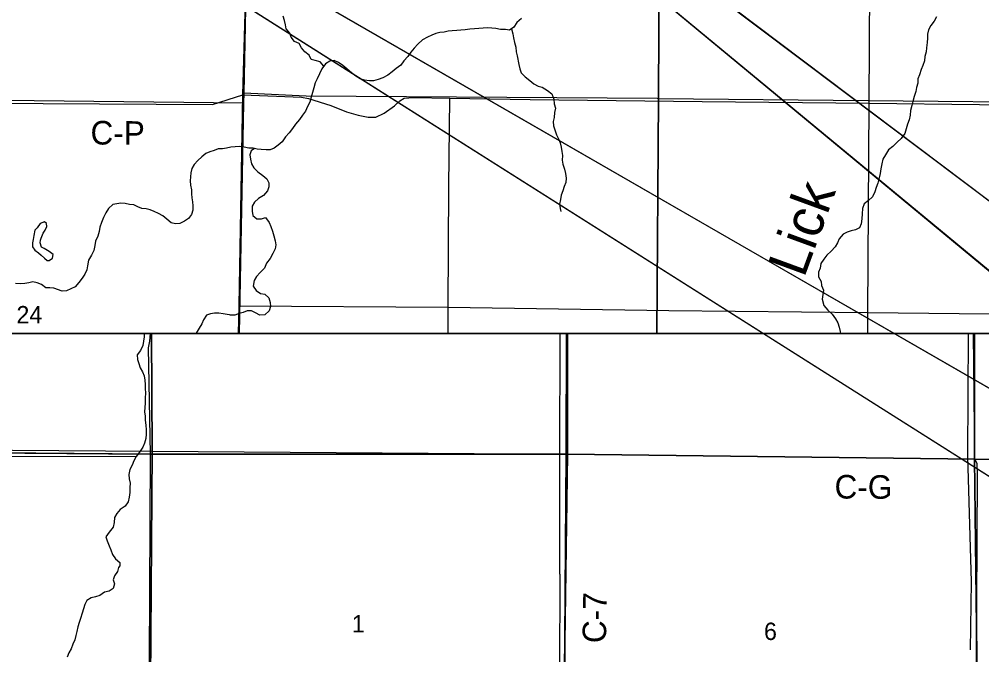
# Model space of a CAD drawing. Extents: x -6.2 to 37.4, y 0.2 to 22.2.
# Drawn here: x 6.554 to 7.714, y 17.321 to 18.086 of the extents above; entities that cross this region are included whole.
import ezdxf

# ---------------------------------------------------------------- set-up
doc = ezdxf.new("R2010")
doc.units = 0
for name, color, linetype in [('GM_X_County_Road', 7, 'Continuous'), ('GM_X_County_Road_Text', 7, 'Continuous'), ('GM_X_Minor_Lake', 7, 'Continuous'), ('GM_X_Minor_River', 7, 'Continuous'), ('GM_X_Minor_River_Text', 7, 'Continuous'), ('GM_X_Rail_Line', 7, 'Continuous'), ('GM_X_Section', 7, 'Continuous'), ('GM_X_Section_Text', 7, 'Continuous'), ('GM_X_Township_Road', 7, 'Continuous'), ('GM_X_US_Shield', 7, 'Continuous'), ('SH_Border', 7, 'Continuous'), ('SH_Cut_Line', 7, 'Continuous'), ('SH_Data', 7, 'Continuous')]:
    doc.layers.add(name, color=color, linetype=linetype)

msp = doc.modelspace()

# ---------------------------------------------------------------- linework, layer by layer
at = {"layer": 'GM_X_County_Road'}
for p, q in [((7.215, 17.5619), (7.2148, 17.7074)), ((7.7056, 17.556), (7.704, 17.7074)), ((7.2115, 17.3074), (7.215, 17.5619))]:
    msp.add_line(p, q, dxfattribs=at)
for points in [[(6.8186, 17.7074), (6.8192, 17.7406), (6.8236, 17.9946), (6.8304, 18.2331)], [(5.443, 17.9975), (5.458, 17.9973), (5.8185, 17.9939), (6.0806, 17.9898), (6.319, 17.9868), (6.5828, 17.9842), (6.7869, 17.983), (6.8236, 17.9946)], [(6.8236, 17.9946), (6.8942, 17.9919), (6.9025, 17.9903), (6.9295, 17.982), (6.9486, 17.9742), (6.9624, 17.9704), (6.9745, 17.9678), (6.9839, 17.9677), (6.994, 17.9727), (7.0064, 17.9815), (7.0126, 17.9877), (7.0179, 17.9909), (7.0293, 17.9915), (7.0729, 17.9907), (7.1697, 17.989), (7.3771, 17.9867), (7.5783, 17.9846)], [(7.5783, 17.9846), (7.8443, 17.9813), (8.1256, 17.9795), (8.3325, 17.9775)], [(6.7121, 17.5619), (6.7098, 17.69), (6.7113, 17.6982), (6.7121, 17.7074)], [(6.2071, 17.5661), (6.7121, 17.5619), (7.215, 17.5619)], [(6.7103, 17.0648), (6.7112, 17.3138), (6.7121, 17.5619)], [(7.215, 17.5619), (7.7056, 17.556), (7.9868, 17.5522), (8.2114, 17.551)], [(7.7089, 17.0636), (7.7076, 17.3026), (7.7087, 17.5373), (7.7083, 17.5507), (7.7056, 17.556)]]:
    msp.add_lwpolyline(points, dxfattribs=at)
at = {"layer": 'GM_X_Minor_Lake'}
msp.add_line((6.581, 17.8112), (6.5792, 17.8166), dxfattribs=at)
msp.add_lwpolyline([(6.5792, 17.8166), (6.5797, 17.8196), (6.5805, 17.8222), (6.5829, 17.8281), (6.5852, 17.8316), (6.5874, 17.8361), (6.5871, 17.8397), (6.5845, 17.8417), (6.5795, 17.8397), (6.5755, 17.8345), (6.5729, 17.8317), (6.5717, 17.8254), (6.5708, 17.8205), (6.5702, 17.8165), (6.5701, 17.8116), (6.573, 17.8078), (6.5775, 17.8043), (6.5804, 17.8015), (6.5847, 17.798), (6.5879, 17.7951), (6.5903, 17.7951), (6.5942, 17.7979), (6.595, 17.8024), (6.59, 17.8061), (6.584, 17.8096), (6.581, 17.8112)], dxfattribs=at)
at = {"layer": 'GM_X_Minor_River'}
for points in [[(7.1595, 18.0865), (7.1537, 18.0819), (7.1502, 18.0761), (7.1448, 18.0727), (7.1399, 18.0734), (7.134, 18.0735), (7.1286, 18.0747), (7.1236, 18.075), (7.1182, 18.0754), (7.1132, 18.0751), (7.1081, 18.0747), (7.1028, 18.0742), (7.0971, 18.0737), (7.0916, 18.073), (7.0864, 18.0724), (7.0815, 18.0722), (7.0758, 18.0718), (7.0709, 18.0713), (7.0661, 18.0702), (7.061, 18.0697), (7.056, 18.0687), (7.0513, 18.0667), (7.0459, 18.0641), (7.0402, 18.0611), (7.0346, 18.0559), (7.0301, 18.0509), (7.0261, 18.046), (7.0224, 18.0409), (7.0174, 18.0357), (7.0139, 18.0304), (7.0085, 18.0265), (7.0037, 18.0223), (6.9983, 18.0186), (6.9924, 18.0154), (6.9865, 18.0131), (6.9811, 18.0116), (6.976, 18.0115), (6.9703, 18.0124), (6.9649, 18.014), (6.9598, 18.0173), (6.9544, 18.0212), (6.949, 18.026), (6.9441, 18.0302), (6.9388, 18.0336), (6.9338, 18.0359), (6.9283, 18.0352), (6.9233, 18.0321), (6.9186, 18.0259), (6.9161, 18.0199), (6.9131, 18.014), (6.9108, 18.0092), (6.9093, 18.0033), (6.9073, 17.9974), (6.9059, 17.9918), (6.9043, 17.9861), (6.9016, 17.9808), (6.899, 17.9752), (6.8953, 17.9701), (6.892, 17.9651), (6.8872, 17.9596), (6.8835, 17.954), (6.8792, 17.9491), (6.8751, 17.9441), (6.8711, 17.9383), (6.8663, 17.934), (6.8615, 17.9304), (6.8565, 17.9286), (6.8518, 17.9285), (6.8457, 17.929), (6.8408, 17.9293), (6.8359, 17.9307), (6.8309, 17.9306), (6.8253, 17.9318), (6.82, 17.9324), (6.8143, 17.9321)], [(6.9211, 18.0292), (6.9167, 18.0343), (6.9108, 18.0359), (6.9059, 18.0373), (6.9035, 18.0423), (6.8983, 18.0465), (6.8942, 18.0515), (6.8913, 18.0565), (6.8858, 18.0589), (6.8817, 18.0641), (6.8801, 18.069), (6.8758, 18.0742), (6.8748, 18.079), (6.8737, 18.0841), (6.8723, 18.0893)], [(7.6596, 18.0885), (7.6565, 18.0835), (7.6525, 18.0784), (7.6499, 18.0728), (7.6487, 18.0676), (7.6486, 18.0629), (7.6481, 18.0578), (7.6474, 18.0513), (7.6472, 18.0466)], [(7.1474, 18.0743), (7.1489, 18.0681), (7.1498, 18.0632), (7.151, 18.0578), (7.1525, 18.0523), (7.1531, 18.0466), (7.1542, 18.0418), (7.1561, 18.0314), (7.1573, 18.026), (7.1589, 18.0213), (7.1636, 18.0163), (7.1694, 18.012), (7.1744, 18.0079), (7.1795, 18.0052), (7.1844, 18.0038), (7.1908, 17.9999), (7.1959, 17.9958), (7.1984, 17.9895), (7.1989, 17.9838), (7.2003, 17.9787), (7.1993, 17.9734), (7.1986, 17.9675), (7.1974, 17.9626), (7.198, 17.9575), (7.2, 17.9513), (7.2015, 17.9466), (7.204, 17.9418), (7.206, 17.9368), (7.2071, 17.9317), (7.2081, 17.9265), (7.2086, 17.9218), (7.2083, 17.9161), (7.2092, 17.9112), (7.211, 17.9054), (7.2124, 17.8999), (7.2131, 17.8944), (7.2126, 17.8893), (7.2106, 17.8842), (7.209, 17.8791), (7.2072, 17.874), (7.2062, 17.8687), (7.2052, 17.8632), (7.2058, 17.8577), (7.2069, 17.8541)], [(7.6472, 18.0466), (7.6456, 18.0409), (7.6449, 18.0358), (7.6429, 18.0302), (7.6409, 18.0251), (7.6389, 18.019), (7.6371, 18.0138), (7.6371, 18.0088), (7.6353, 18.0035), (7.6346, 17.9986), (7.6324, 17.9928), (7.6308, 17.9869), (7.6298, 17.982), (7.6283, 17.9759), (7.6279, 17.9701), (7.6266, 17.9646), (7.6247, 17.9593), (7.6229, 17.9538), (7.6212, 17.9483), (7.617, 17.9422), (7.612, 17.9379), (7.6068, 17.9326), (7.6018, 17.9287), (7.5979, 17.9225), (7.5949, 17.9173), (7.5935, 17.9118), (7.5925, 17.9055), (7.5916, 17.9002), (7.5902, 17.8946), (7.5886, 17.8882), (7.5868, 17.8832), (7.5852, 17.878), (7.5824, 17.8719), (7.5776, 17.8673), (7.5724, 17.8634), (7.5702, 17.8577), (7.5699, 17.8513), (7.5696, 17.8456), (7.5686, 17.8393), (7.5668, 17.8344), (7.5618, 17.832), (7.5567, 17.8308), (7.5517, 17.8294), (7.5468, 17.827), (7.5423, 17.8215), (7.5403, 17.8166), (7.5374, 17.8116), (7.5324, 17.8063), (7.5274, 17.8017), (7.5237, 17.7968), (7.52, 17.7915), (7.5191, 17.786), (7.5174, 17.7811), (7.5173, 17.7756), (7.5206, 17.7699), (7.5209, 17.765), (7.5231, 17.7596), (7.5226, 17.7543), (7.5217, 17.7486), (7.5235, 17.7412), (7.5287, 17.7356), (7.5336, 17.7308), (7.5378, 17.7252), (7.5406, 17.7202), (7.5422, 17.7151), (7.5433, 17.7097), (7.5439, 17.7074)], [(6.8143, 17.9321), (6.8091, 17.9316), (6.804, 17.9306), (6.7991, 17.9298), (6.794, 17.9297), (6.789, 17.9279), (6.7839, 17.9261), (6.7791, 17.9241), (6.7743, 17.9202), (6.7694, 17.9157), (6.7648, 17.9109), (6.7621, 17.906), (6.7608, 17.9009), (6.7603, 17.896), (6.7602, 17.8911), (6.7605, 17.8858), (6.7617, 17.8804), (6.7618, 17.8755), (6.7619, 17.8708), (6.7627, 17.8658), (6.7634, 17.861), (6.7631, 17.8559), (6.7615, 17.8508), (6.758, 17.846), (6.7532, 17.8425), (6.7476, 17.8399), (6.7425, 17.8393), (6.7372, 17.8407), (6.7318, 17.845), (6.727, 17.8489), (6.7219, 17.8518), (6.7167, 17.8542), (6.7118, 17.8562), (6.7069, 17.8576), (6.7018, 17.8579), (6.6969, 17.8599), (6.6921, 17.8621), (6.687, 17.8628), (6.6817, 17.8638), (6.6766, 17.8641), (6.6718, 17.8636), (6.6669, 17.8628), (6.6617, 17.858), (6.6585, 17.8527), (6.6556, 17.8469), (6.6534, 17.8412), (6.6514, 17.8354), (6.6503, 17.8301), (6.6489, 17.8245), (6.6459, 17.8186), (6.6452, 17.8133), (6.6438, 17.8073), (6.6412, 17.8018), (6.6377, 17.7957), (6.6364, 17.789), (6.6357, 17.7839), (6.6332, 17.7789), (6.63, 17.774), (6.6259, 17.7686), (6.6215, 17.7634), (6.6163, 17.761), (6.6112, 17.7586), (6.6057, 17.7582), (6.5959, 17.7618), (6.591, 17.7624), (6.5861, 17.7624), (6.5808, 17.7664), (6.5758, 17.7683), (6.5705, 17.7695), (6.5656, 17.7683), (6.5608, 17.7674), (6.5557, 17.7671), (6.5496, 17.7674)], [(6.8375, 17.9302), (6.8337, 17.9275), (6.8321, 17.9224), (6.8326, 17.9172), (6.834, 17.9117), (6.8368, 17.9067), (6.8418, 17.9021), (6.8476, 17.8976), (6.8525, 17.8936), (6.8547, 17.8888), (6.8548, 17.8841), (6.8532, 17.879), (6.8485, 17.8735), (6.8426, 17.8698), (6.8376, 17.8654), (6.8349, 17.8605), (6.8348, 17.8546), (6.8354, 17.8496), (6.8405, 17.8456), (6.846, 17.8455), (6.8507, 17.8471), (6.8554, 17.8412), (6.8572, 17.8362), (6.8592, 17.8305), (6.8608, 17.8249), (6.8626, 17.819), (6.8633, 17.8143), (6.8624, 17.8094), (6.8597, 17.8037), (6.8565, 17.7977), (6.8519, 17.7921), (6.8497, 17.7862), (6.8445, 17.781), (6.8399, 17.7761), (6.8371, 17.7712), (6.8359, 17.7644), (6.8398, 17.7592), (6.8448, 17.7557), (6.8501, 17.7549), (6.8548, 17.7501), (6.8564, 17.7446), (6.8569, 17.7398), (6.8551, 17.7347), (6.8501, 17.7299), (6.844, 17.7294), (6.8387, 17.7321), (6.8339, 17.7347), (6.8287, 17.7348), (6.824, 17.7327), (6.819, 17.7313), (6.8139, 17.7294), (6.8087, 17.7294), (6.8074, 17.7298)], [(6.8074, 17.7298), (6.8047, 17.7303), (6.7997, 17.7309), (6.7946, 17.7318), (6.7894, 17.7317), (6.7847, 17.7311), (6.7799, 17.7294), (6.776, 17.724), (6.774, 17.7189), (6.7709, 17.7137), (6.7672, 17.7077), (6.7671, 17.7074)], [(6.7047, 17.7074), (6.7045, 17.7035), (6.704, 17.6982), (6.7029, 17.6929), (6.7002, 17.6867), (6.6961, 17.6817), (6.6967, 17.6762), (6.6982, 17.6711), (6.7, 17.6659), (6.7028, 17.6611), (6.7046, 17.6563), (6.7056, 17.6513), (6.706, 17.6458), (6.706, 17.641), (6.7062, 17.6355), (6.7057, 17.63), (6.7059, 17.6236), (6.7053, 17.6183), (6.7052, 17.613), (6.7058, 17.6078), (6.706, 17.6029), (6.7068, 17.597), (6.707, 17.5913), (6.707, 17.5862), (6.7065, 17.5809), (6.7052, 17.5754), (6.7032, 17.5704), (6.699, 17.5644), (6.6949, 17.5594), (6.6922, 17.5542)], [(7.2054, 17.4176), (7.2056, 17.5579), (7.206, 17.7074)], [(7.6975, 17.7074), (7.6967, 17.5596), (7.7013, 17.4082)], [(6.6949, 17.5594), (6.4592, 17.5589), (6.4575, 17.4411), (6.4298, 17.4394), (6.4295, 17.4377), (6.4304, 17.4347), (6.429, 17.4326), (6.4282, 17.4303)], [(6.6922, 17.5542), (6.69, 17.5487), (6.6874, 17.5435), (6.6862, 17.5376), (6.6865, 17.5325), (6.6876, 17.527), (6.6875, 17.5219), (6.6875, 17.516), (6.6866, 17.5103), (6.6852, 17.5045), (6.6817, 17.4993), (6.6759, 17.4956), (6.6717, 17.4906), (6.6689, 17.4856), (6.6684, 17.4799), (6.6671, 17.4741), (6.6625, 17.4683), (6.6586, 17.4627), (6.66, 17.4578), (6.6624, 17.4516), (6.6646, 17.4468), (6.6663, 17.4411), (6.6699, 17.436), (6.6753, 17.4317), (6.6753, 17.4276), (6.6738, 17.4255)], [(6.6738, 17.4255), (6.6725, 17.4206), (6.669, 17.4157), (6.6674, 17.4106), (6.6688, 17.4058), (6.6672, 17.4002), (6.6624, 17.397), (6.6568, 17.3958), (6.6514, 17.3919), (6.6461, 17.3902), (6.6409, 17.3891), (6.6357, 17.386), (6.6332, 17.3809), (6.6317, 17.3758), (6.6299, 17.3707), (6.6279, 17.3643), (6.6263, 17.3592), (6.6246, 17.3543), (6.6234, 17.3485), (6.6223, 17.3436), (6.6211, 17.3383), (6.6187, 17.3332), (6.6165, 17.3277), (6.6139, 17.3227), (6.6117, 17.3176)], [(7.2054, 17.4176), (7.2051, 17.2996), (7.2042, 17.0555), (7.2042, 16.6122), (7.2027, 16.5056), (7.1415, 16.5229)], [(7.7013, 17.4082), (7.6999, 17.3265)]]:
    msp.add_lwpolyline(points, dxfattribs=at)
at = {"layer": 'GM_X_Rail_Line'}
for points in [[(6.8303, 18.2334), (6.8234, 17.9949), (6.8191, 17.7409), (6.8185, 17.7074), (8.4809, 17.7074), (8.4809, 19.1054)], [(5.0809, 17.7074), (6.8185, 17.7074), (6.8191, 17.7409), (6.8234, 17.9949), (6.8303, 18.2334), (6.8306, 18.2466), (6.8333, 18.3833), (6.839, 18.606), (6.8377, 18.6726), (6.8089, 18.6833), (6.769, 18.7036), (6.7158, 18.727), (6.6958, 18.7366), (6.6777, 18.7471), (6.6321, 18.7693), (6.6178, 18.7761), (6.6077, 18.7802), (6.5746, 18.7941), (6.5463, 18.8048)], [(7.1964, 15.5569), (7.1984, 15.7978), (7.1999, 16.0487), (7.2, 16.0578), (7.2064, 16.5582), (7.2085, 17.0529), (7.2085, 17.0597), (7.2111, 17.301), (7.2113, 17.3076), (7.2148, 17.5622), (6.712, 17.5622), (6.207, 17.5663), (5.7029, 17.5702), (5.2018, 17.5825), (5.0809, 17.5845), (5.0809, 14.5732)], [(8.4809, 14.5412), (8.4809, 17.5483), (8.2113, 17.5513), (7.7055, 17.5562), (7.2148, 17.5622), (7.2113, 17.3076), (7.2111, 17.301), (7.2085, 17.0597), (7.2085, 17.0529), (7.2064, 16.5582), (7.2, 16.0578), (7.1999, 16.0487), (7.1984, 15.7978), (7.1964, 15.5569)]]:
    msp.add_lwpolyline(points, dxfattribs=at)
for points in [[(7.2147, 17.7074), (5.0809, 17.7074), (5.0809, 17.5845), (5.2018, 17.5825), (5.7029, 17.5702), (6.207, 17.5663), (6.712, 17.5622), (7.2148, 17.5622)], [(8.4809, 17.5483), (8.4809, 17.7074), (7.2147, 17.7074), (7.2148, 17.5622), (7.7055, 17.5562), (8.2113, 17.5513)]]:
    msp.add_lwpolyline(points, close=True, dxfattribs=at)
at = {"layer": 'GM_X_Section'}
for points in [[(6.3315, 18.4914), (6.8344, 18.4859), (6.8247, 17.9967), (6.8243, 17.9846), (6.3196, 17.9903)], [(6.8351, 18.4992), (7.3269, 18.4925), (7.3244, 17.9901), (7.3227, 17.9903), (6.8997, 17.9933), (6.8247, 17.9967), (6.8344, 18.4859)], [(7.3269, 18.4925), (7.8385, 18.4884), (7.8298, 17.9849), (7.3244, 17.9901)], [(6.2087, 17.5693), (6.7143, 17.5658), (6.7105, 17.0669), (6.2076, 17.0711)], [(6.7143, 17.5658), (7.213, 17.562), (7.2096, 17.0612), (6.7105, 17.0669)], [(7.213, 17.562), (7.7053, 17.5563), (7.7113, 17.0508), (7.2097, 17.0532), (7.2096, 17.0612)], [(7.7053, 17.5563), (8.2095, 17.5519), (8.2148, 17.0483), (7.7113, 17.0508)]]:
    msp.add_lwpolyline(points, close=True, dxfattribs=at)
at = {"layer": 'GM_X_Township_Road'}
for p in [(6.8192, 17.7406), (7.0709, 17.7074)]:
    msp.add_line(p, (7.071, 17.7391), dxfattribs=at)
for points in [[(7.5783, 17.9846), (7.5792, 18.1254), (7.5815, 18.2343), (7.5839, 18.3522), (7.5867, 18.4883), (7.5892, 18.7717), (7.592, 18.9957)], [(7.071, 17.7391), (7.0717, 17.8845), (7.0729, 17.9907)], [(7.5766, 17.7074), (7.5767, 17.7325), (7.5775, 17.8573), (7.5783, 17.9846)], [(7.071, 17.7391), (7.3368, 17.7352), (7.5767, 17.7325)], [(7.5767, 17.7325), (8.0906, 17.7271), (8.3, 17.7225)]]:
    msp.add_lwpolyline(points, dxfattribs=at)
at = {"layer": 'GM_X_US_Shield'}
for points in [[(6.3135, 17.7074), (6.8193, 17.7074), (6.8243, 17.9846), (6.3196, 17.9903)], [(6.8193, 17.7074), (7.3225, 17.7074), (7.3244, 17.9901), (7.3227, 17.9903), (6.8997, 17.9933), (6.8247, 17.9967), (6.8243, 17.9846)], [(7.3225, 17.7074), (7.8261, 17.7074), (7.8298, 17.9849), (7.3244, 17.9901)], [(6.7133, 17.7074), (6.209, 17.7074), (6.2087, 17.5693), (6.7143, 17.5658)], [(7.2134, 17.7074), (6.7133, 17.7074), (6.7143, 17.5658), (7.213, 17.562)], [(7.7054, 17.7074), (7.2134, 17.7074), (7.213, 17.562), (7.7053, 17.5563)], [(8.2105, 17.7074), (7.7054, 17.7074), (7.7053, 17.5563), (8.2095, 17.5519)]]:
    msp.add_lwpolyline(points, close=True, dxfattribs=at)
at = {"layer": 'SH_Border'}
for p, q in [((5.8368, 18.7275), (8.9944, 16.9093)), ((8.9944, 16.7311), (5.8368, 18.7275)), ((6.5844, 18.7243), (8.9944, 16.9093)), ((8.9944, 16.7311), (6.5844, 18.7243)), ((5.0809, 17.7074), (8.4809, 17.7074))]:
    msp.add_line(p, q, dxfattribs=at)
at = {"layer": 'SH_Cut_Line'}
msp.add_lwpolyline([(8.4809, 14.5412), (8.4809, 17.7074), (5.0809, 17.7074), (5.0809, 14.5732)], dxfattribs=at)
at = {"layer": 'SH_Data'}
for points in [[(8.9944, 16.7311), (5.8368, 18.7275), (8.9944, 16.9093)], [(8.9944, 16.9093), (6.5844, 18.7243), (8.9944, 16.7311)]]:
    msp.add_lwpolyline(points, close=True, dxfattribs=at)

# ---------------------------------------------------------------- texts
at = {"layer": 'GM_X_County_Road_Text'}
for s, rotation, p in [('C-P', 359.5595, (6.6399, 17.935)), ('C-G', 359.6023, (7.5365, 17.5087)), ('C-7', 89.0821, (7.2612, 17.3343))]:
    msp.add_text(s, height=0.02841, rotation=rotation, dxfattribs=at).set_placement(p)
at = {"layer": 'GM_X_Minor_River_Text'}
msp.add_text('Lick', height=0.04738, rotation=69.8801, dxfattribs=at).set_placement((7.4998, 17.7733))
at = {"layer": 'GM_X_Section_Text'}
for s, height, p in [('24', 0.02093, (6.5507, 17.7195)), ('1', 0.0209, (6.9548, 17.3474)), ('6', 0.0209, (7.4516, 17.3383))]:
    msp.add_text(s, height=height, rotation=0, dxfattribs=at).set_placement(p)

doc.saveas('drawing.dxf')
